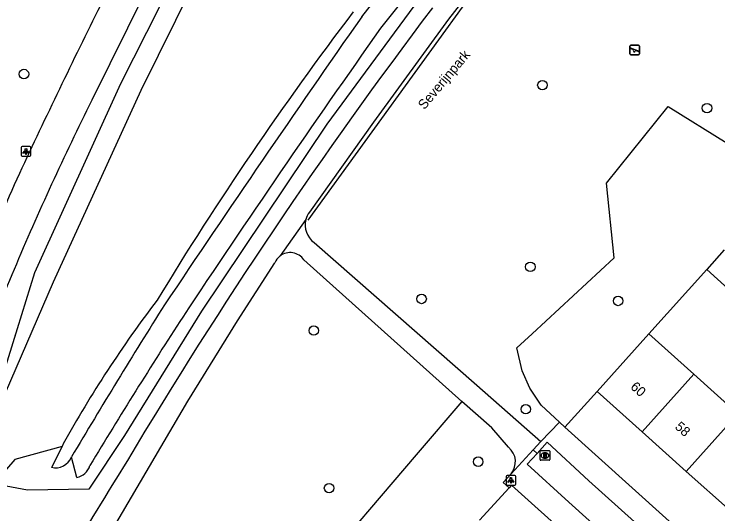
# Model space of a CAD drawing. Extents: x 159040 to 160094, y 381214 to 382518.
# Drawn here: x 159367.1 to 159439.8, y 382088.4 to 382140.1 of the extents above; entities that cross this region are included whole.
import ezdxf

# ---------------------------------------------------------------- set-up
doc = ezdxf.new("R2010")
doc.units = 0
for name, color, linetype in [('IMGEO_Boom', 7, 'Continuous'), ('IMGEO_Fietspad_gesloten', 7, 'Continuous'), ('IMGEO_Groenvoorziening', 7, 'Continuous'), ('IMGEO_Hek', 7, 'Continuous'), ('IMGEO_Lichtpunt', 7, 'Continuous'), ('IMGEO_Meer_plas_ven_vijver', 7, 'Continuous'), ('IMGEO_Openbare_ruimte_label', 7, 'Continuous'), ('IMGEO_Pand', 7, 'Continuous'), ('IMGEO_Pand_nummerreeks', 7, 'Continuous'), ('IMGEO_Rijbaan_lokaal_open', 7, 'Continuous'), ('IMGEO_Rioolput', 7, 'Continuous'), ('IMGEO_Speelvoorziening', 7, 'Continuous'), ('IMGEO_Voetpad_gesloten', 7, 'Continuous'), ('IMGEO_Voetpad_open', 7, 'Continuous')]:
    doc.layers.add(name, color=color, linetype=linetype)

msp = doc.modelspace()

# ---------------------------------------------------------------- linework, layer by layer
at = {"layer": 'IMGEO_Boom'}
for centre in [(159368.115, 382133.897), (159421.684, 382132.754), (159438.698, 382130.372), (159420.442, 382113.976), (159409.208, 382110.658), (159429.512, 382110.451), (159398.062, 382107.391), (159419.967, 382099.266), (159415.053, 382093.845), (159399.639, 382091.116)]:
    msp.add_circle(centre, 0.489, dxfattribs=at)
at = {"layer": 'IMGEO_Fietspad_gesloten'}
msp.add_lwpolyline([(159388.062, 382157.36), (159375.118, 382131.186)], dxfattribs=at)
for centre, radius, start, end in [((160147.437, 381758.607), 861, 153.633098, 154.915239), ((159654.193, 381992.43), 311.667, 153.56354, 157.09927), ((159770.869, 381940.427), 442.894, 155.56493, 158.22317), ((159810.193, 381923.148), 482.341, 156.729, 159.07861)]:
    msp.add_arc(centre, radius, start, end, dxfattribs=at)
at = {"layer": 'IMGEO_Groenvoorziening'}
for points in [[(159364.104, 382092.669), (159362.92, 382093.152), (159369.246, 382113.396), (159378.119, 382132.921), (159387.535, 382151.506), (159399.088, 382173.666), (159408.268, 382188.263)], [(159424.514, 382188.415), (159427.144, 382183.833), (159429.09, 382182.451), (159432.379, 382180.645), (159434.583, 382179.615), (159436.124, 382178.366), (159436.429, 382175.447), (159427.914, 382165.716), (159413.925, 382148.417), (159399.408, 382128.719), (159386.451, 382109.386), (159378.514, 382096.541), (159374.803, 382091.012), (159368.466, 382090.901), (159366.281, 382091.313), (159365.922, 382092.134)], [(159403.013, 382139.809), (159432.043, 382176.774)], [(159434.204, 382176.286), (159433.607, 382174.444), (159404.959, 382138.622)], [(159423.442, 382097.934), (159421.556, 382099.695), (159420.403, 382101.425), (159419.602, 382103.218), (159419.033, 382105.59), (159420.624, 382107.039), (159429.12, 382114.911), (159428.315, 382122.632), (159434.692, 382130.55), (159440.797, 382126.746), (159447.77, 382133.461), (159453.41, 382139.902)], [(159438.669, 382113.699), (159432.686, 382107.057)], [(159427.345, 382101.105), (159424.019, 382097.413)], [(159413.377, 382100.065), (159408.66, 382094.544), (159387.365, 382069.622), (159385.857, 382070.936)], [(159372.05, 382095.426), (159370.949, 382093.26)], [(159373.57, 382092.204), (159373.024, 382094.328)], [(159418.239, 382091.137), (159415.202, 382087.803)]]:
    msp.add_lwpolyline(points, dxfattribs=at)
for centre, radius, start, end in [((160854.298, 381124.423), 1771.225, 145.0216, 146.188315), ((160450.54, 381400.124), 1280.085, 144.766282, 146.385082), ((159941.525, 381757.41), 660.838, 147.749459, 149.347191), ((159889.716, 381782.72), 601.291, 147.160781, 148.885497), ((159371.375, 382094.983), 1.774, 256.11767, 338.35198), ((159373.191, 382093.987), 1.823, 281.99129, 342.44267)]:
    msp.add_arc(centre, radius, start, end, dxfattribs=at)
at = {"layer": 'IMGEO_Hek'}
msp.add_lwpolyline([(159397.488, 382118.797), (159415.14, 382143.214)], dxfattribs=at)
at = {"layer": 'IMGEO_Lichtpunt'}
for p, q in [((159367.825, 382126.304), (159367.825, 382125.497)), ((159367.825, 382126.304), (159367.825, 382125.497)), ((159368.727, 382126.399), (159367.919, 382126.399)), ((159368.727, 382126.399), (159367.919, 382126.399)), ((159368.821, 382125.497), (159368.821, 382126.304)), ((159368.821, 382125.497), (159368.821, 382126.304)), ((159367.919, 382125.403), (159368.727, 382125.403)), ((159367.919, 382125.403), (159368.727, 382125.403)), ((159417.941, 382092.329), (159417.941, 382091.522)), ((159417.941, 382092.329), (159417.941, 382091.522)), ((159418.843, 382092.424), (159418.035, 382092.424)), ((159418.843, 382092.424), (159418.035, 382092.424)), ((159418.937, 382091.522), (159418.937, 382092.329)), ((159418.937, 382091.522), (159418.937, 382092.329)), ((159418.035, 382091.428), (159418.843, 382091.428)), ((159418.035, 382091.428), (159418.843, 382091.428))]:
    msp.add_line(p, q, dxfattribs=at)
for points in [[(159368.199, 382125.968), (159368.238, 382125.94), (159368.05, 382125.678), (159368.012, 382125.705), (159368.199, 382125.968)], [(159368.301, 382125.92), (159368.348, 382125.92), (159368.348, 382125.598), (159368.301, 382125.598), (159368.301, 382125.92)], [(159368.411, 382125.94), (159368.449, 382125.967), (159368.636, 382125.705), (159368.597, 382125.677), (159368.411, 382125.94)], [(159418.315, 382091.993), (159418.354, 382091.965), (159418.166, 382091.703), (159418.128, 382091.73), (159418.315, 382091.993)], [(159418.527, 382091.965), (159418.565, 382091.992), (159418.752, 382091.73), (159418.713, 382091.702), (159418.527, 382091.965)], [(159418.417, 382091.945), (159418.464, 382091.945), (159418.464, 382091.623), (159418.417, 382091.623), (159418.417, 382091.945)]]:
    msp.add_lwpolyline(points, dxfattribs=at)
for centre in [(159368.324, 382126.102), (159418.44, 382092.127)]:
    msp.add_circle(centre, 0.0994, dxfattribs=at)
for centre, start, end in [((159367.919, 382126.304), 90, 180), ((159367.919, 382126.304), 90, 180), ((159368.727, 382126.304), 0, 90), ((159368.727, 382126.304), 0, 90), ((159367.919, 382125.497), 180, 270), ((159367.919, 382125.497), 180, 270), ((159368.727, 382125.497), 270, 0), ((159368.727, 382125.497), 270, 360), ((159418.035, 382092.329), 90, 180), ((159418.035, 382092.329), 90, 180), ((159418.843, 382092.329), 0, 90), ((159418.843, 382092.329), 0, 90), ((159418.035, 382091.522), 180, 270), ((159418.035, 382091.522), 180, 270), ((159418.843, 382091.522), 270, 0), ((159418.843, 382091.522), 270, 360)]:
    msp.add_arc(centre, 0.0946, start, end, dxfattribs=at)
at = {"layer": 'IMGEO_Meer_plas_ven_vijver'}
for points in [[(159364.739, 382092.675), (159365.059, 382098.418), (159371.182, 382112.41), (159380.224, 382132.238), (159389.22, 382150.415), (159400.964, 382172.686), (159409.272, 382187.122)], [(159372.176, 382095.675), (159372.05, 382095.426)], [(159372.05, 382095.426), (159367.168, 382094.07), (159365.662, 382092.326)]]:
    msp.add_lwpolyline(points, dxfattribs=at)
for centre, radius, start, end in [((159674.386, 381933.239), 342.05, 142.74049, 148.7828), ((159478.564, 382036.832), 121.577, 142.69292, 151.05308)]:
    msp.add_arc(centre, radius, start, end, dxfattribs=at)
at = {"layer": 'IMGEO_Pand'}
for points in [[(159440.485, 382115.723), (159438.669, 382113.699)], [(159442.855, 382112.454), (159441.607, 382111.063), (159438.669, 382113.699)], [(159427.345, 382101.105), (159432.686, 382107.057)], [(159432.686, 382107.057), (159437.336, 382102.884)], [(159431.994, 382096.933), (159437.336, 382102.884)], [(159437.336, 382102.884), (159441.895, 382098.793)], [(159431.994, 382096.933), (159427.345, 382101.105)], [(159436.554, 382092.841), (159441.895, 382098.793)], [(159436.554, 382092.841), (159431.994, 382096.933)], [(159441.114, 382088.749), (159436.554, 382092.841)]]:
    msp.add_lwpolyline(points, dxfattribs=at)
at = {"layer": 'IMGEO_Rijbaan_lokaal_open'}
for points in [[(159421.139, 382094.706), (159422.172, 382095.85), (159426.476, 382091.859), (159439.286, 382080.355), (159447.544, 382072.913)], [(159421.139, 382094.706), (159420.122, 382093.578), (159424.405, 382089.668), (159432.474, 382082.409), (159445.513, 382070.713)]]:
    msp.add_lwpolyline(points, dxfattribs=at)
at = {"layer": 'IMGEO_Rioolput'}
for p, q in [((159421.448, 382094.064), (159421.448, 382094.916)), ((159421.523, 382094.99), (159422.375, 382094.99)), ((159422.449, 382094.916), (159422.449, 382094.064)), ((159421.959, 382094.21), (159421.934, 382094.21)), ((159421.936, 382094.77), (159421.961, 382094.77)), ((159422.375, 382093.99), (159421.523, 382093.99))]:
    msp.add_line(p, q, dxfattribs=at)
for points in [[(159421.448, 382094.064), (159421.448, 382094.916)], [(159421.523, 382094.99), (159422.375, 382094.99)], [(159422.449, 382094.916), (159422.449, 382094.064)], [(159422.037, 382094.688), (159421.785, 382094.69), (159421.785, 382094.29)], [(159421.785, 382094.29), (159421.909, 382094.29), (159421.909, 382094.452), (159421.92, 382094.452)], [(159421.963, 382094.609), (159421.909, 382094.609), (159421.909, 382094.528)], [(159421.909, 382094.528), (159421.961, 382094.528)], [(159421.967, 382094.423), (159422.038, 382094.29), (159422.178, 382094.29), (159422.113, 382094.416)], [(159422.375, 382093.99), (159421.523, 382093.99)]]:
    msp.add_lwpolyline(points, dxfattribs=at)
for centre, radius, start, end in [((159421.525, 382094.914), 0.0765, 91.55205, 178.44795), ((159421.525, 382094.914), 0.0765, 91.55205, 178.44795), ((159422.373, 382094.914), 0.0765, 1.55205, 88.44795), ((159422.373, 382094.914), 0.0765, 1.55205, 88.44795), ((159421.919, 382094.399), 0.0533, 26.02933, 88.69889), ((159421.945, 382094.717), 0.19, 274.7715, 282.96867), ((159421.969, 382094.513), 0.0964, 77.00612, 93.18647), ((159421.983, 382094.57), 0.0378, 276.66336, 79.67722), ((159422.036, 382094.578), 0.109, 350.36119, 89.41601), ((159422.034, 382094.578), 0.112, 277.58423, 350.98172), ((159422.018, 382094.363), 0.108, 29.51342, 73.79051), ((159421.525, 382094.066), 0.0765, 181.55205, 268.44795), ((159421.525, 382094.066), 0.0765, 181.55205, 268.44795), ((159422.373, 382094.066), 0.0765, 271.55205, 358.44795), ((159422.373, 382094.066), 0.0765, 271.55205, 358.44795)]:
    msp.add_arc(centre, radius, start, end, dxfattribs=at)
for centre, major_axis, ratio, start_param, end_param in [((159421.935, 382094.49), (-0.387, 0.002), 0.722429, 4.712389, 7.853982), ((159421.96, 382094.49), (-0.39, 0.002), 0.717154, 1.570796, 4.712389)]:
    msp.add_ellipse(centre, major_axis=major_axis, ratio=ratio, start_param=start_param, end_param=end_param, dxfattribs=at)
at = {"layer": 'IMGEO_Speelvoorziening'}
for p, q in [((159430.728, 382135.975), (159430.728, 382136.775)), ((159430.728, 382136.775), (159430.728, 382135.975)), ((159431.111, 382136.403), (159430.772, 382136.54)), ((159430.797, 382136.6), (159431.673, 382136.247)), ((159430.828, 382136.875), (159431.618, 382136.875)), ((159431.618, 382136.875), (159430.828, 382136.875)), ((159431.649, 382136.187), (159431.309, 382136.324)), ((159431.718, 382136.775), (159431.718, 382135.975)), ((159431.718, 382135.975), (159431.718, 382136.775)), ((159431.618, 382135.875), (159430.828, 382135.875)), ((159430.828, 382135.875), (159431.618, 382135.875))]:
    msp.add_line(p, q, dxfattribs=at)
for centre, radius, start, end in [((159430.828, 382136.775), 0.1, 90, 180), ((159430.828, 382136.775), 0.1, 90, 180), ((159430.785, 382136.57), 0.0327, 68.07798, 248.07798), ((159431.19, 382136.313), 0.12, 130.99278, 5.16318), ((159431.618, 382136.775), 0.1, 0, 90), ((159431.618, 382136.775), 0.1, 360, 90), ((159430.828, 382135.975), 0.1, 180, 270), ((159430.828, 382135.975), 0.1, 180, 270), ((159431.618, 382135.975), 0.1, 270, 0), ((159431.618, 382135.975), 0.1, 270, 0), ((159431.661, 382136.217), 0.0327, 248.07798, 68.07798)]:
    msp.add_arc(centre, radius, start, end, dxfattribs=at)
at = {"layer": 'IMGEO_Voetpad_gesloten'}
for points in [[(159419.901, 382149.722), (159411.987, 382139.576), (159404.234, 382128.932), (159397.604, 382119.622)], [(159397.239, 382118.857), (159394.578, 382115.102)], [(159398.091, 382116.491), (159414.906, 382101.741), (159421.535, 382095.926)], [(159397.037, 382114.689), (159413.377, 382100.065)], [(159373.992, 382081.27), (159385.031, 382100.107), (159390.166, 382108.397), (159394.028, 382114.374)], [(159418.2, 382095.331), (159416.462, 382097.35), (159413.377, 382100.065)], [(159421.535, 382095.926), (159420.742, 382095.065)], [(159420.742, 382095.065), (159418.453, 382092.583)]]:
    msp.add_lwpolyline(points, dxfattribs=at)
for centre, radius, start, end in [((159813.221, 381835.149), 505.669, 142.81805, 149.21492), ((159399.406, 382118.293), 2.239, 143.58139, 165.40474), ((159399.392, 382118.296), 2.225, 165.38831, 234.21973), ((159395.615, 382113.748), 1.705, 33.4951, 127.43671), ((159395.613, 382113.748), 1.704, 127.40157, 158.45674), ((159416.94, 382093.829), 1.96, 320.51924, 50.0012), ((159702.63, 381890.619), 382.375, 147.87389, 151.49088)]:
    msp.add_arc(centre, radius, start, end, dxfattribs=at)
at = {"layer": 'IMGEO_Voetpad_open'}
for points in [[(159423.442, 382097.934), (159421.535, 382095.926)], [(159424.019, 382097.413), (159423.442, 382097.934)], [(159424.019, 382097.413), (159447.998, 382075.782)], [(159420.742, 382095.065), (159421.139, 382094.706)], [(159418.239, 382091.137), (159417.632, 382091.692), (159418.453, 382092.583)], [(159442.459, 382069.847), (159418.503, 382091.427), (159418.239, 382091.137)]]:
    msp.add_lwpolyline(points, dxfattribs=at)

# ---------------------------------------------------------------- texts
at = {"layer": 'IMGEO_Openbare_ruimte_label'}
msp.add_text('Severijnpark', height=1, rotation=49.90832, dxfattribs=at).set_placement((159409.498, 382130.158))
at = {"layer": 'IMGEO_Pand_nummerreeks'}
for s, p in [('60', (159430.713, 382101.468)), ('58', (159435.308, 382097.345))]:
    msp.add_text(s, height=1, rotation=318.09473, dxfattribs=at).set_placement(p)

doc.saveas('drawing.dxf')
